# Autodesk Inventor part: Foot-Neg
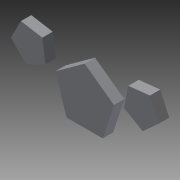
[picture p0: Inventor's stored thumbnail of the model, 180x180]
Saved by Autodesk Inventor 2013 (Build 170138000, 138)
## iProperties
Created: 2013-04
Part Number: Foot-Neg
Material: Generic
Document SubType Name: Modeling
Designer: frankenteddy
Density: 1 g/cm^3
Author: frankenteddy
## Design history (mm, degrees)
sketch "Sketch1"
  geometry: L1 (7.563, 8.864)-(8.164, 13.005); L2 (11.316, 7.012)-(7.563, 8.864); L3 (8.164, 13.005)-(12.289, 13.713); L4 (14.237, 10.009)-(11.316, 7.012); L5 (12.289, 13.713)-(14.237, 10.009); L6 (3.487, 2.02)-(-3.487, 2.02); L7 (0, 12.753)-(5.643, 8.653); L8 (5.643, 8.653)-(3.487, 2.02); L9 (-3.487, 2.02)-(-5.643, 8.653); L10 (-5.643, 8.653)-(0, 12.753); L11 (-8.414, 13.257)-(-7.563, 9.159); L12 (-7.563, 9.159)-(-11.196, 7.083); L13 (-11.196, 7.083)-(-14.294, 9.897); L14 (-14.294, 9.897)-(-12.574, 13.713); L15 (-12.574, 13.713)-(-8.414, 13.257); 4 further points
  constraints: 30 end point, 33 other
  dimensions: "d0" = 2.88 distance from line of point (-10.808, 10.622) L13; "d1" = 2.88 distance from line of point (10.714, 10.52) L2; "d2" = 4.8 distance from line of point (0, 6.82) L6; "d3" = 1.92 horizontal distance of L9.end L11.end; "d4" = 1.92 horizontal distance of L1.start L7.end
extrude "Extrusion1" new body sketch "Sketch1" distance "d5" = 2; taper "d6" = 0 deg
body "Solid1"
